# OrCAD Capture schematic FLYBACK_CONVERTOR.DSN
size A
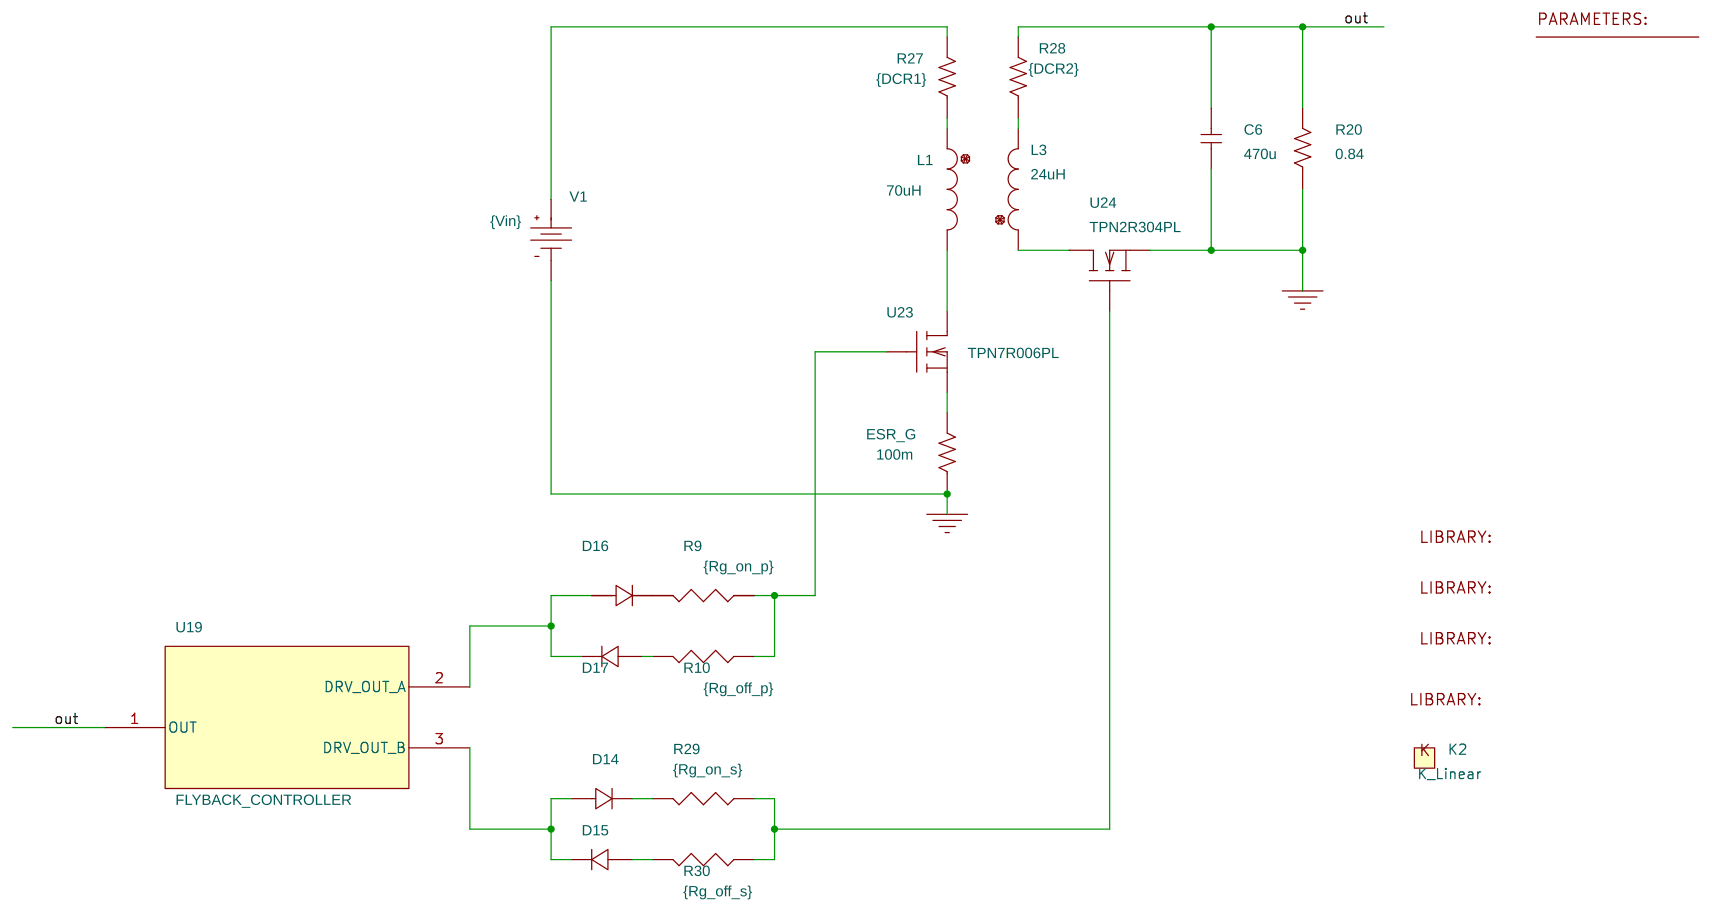
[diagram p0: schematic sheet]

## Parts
1  PARAM
C6  470u  [cap196]
D14  Diode_nom
D15  Diode_nom
D16  Diode_nom
D17  Diode_nom
ESR_G  100m  [AXRC05]
K2  K_Linear
L1  70uH  [DISC350x175LS200x100034]
L3  24uH  [DISC350x175LS200x100034]
LIB1  LIB
LIB2  LIB
LIB3  LIB
LIB4  LIB
R9  {Rg_on_p}  [AXRC05]
R10  {Rg_off_p}  [AXRC05]
R20  0.84  [AXRC05]
R27  {DCR1}  [AXRC05]
R28  {DCR2}  [AXRC05]
R29  {Rg_on_s}  [AXRC05]
R30  {Rg_off_s}  [AXRC05]
U19  FLYBACK_CONTROLLER
U23  TPN7R006PL
U24  TPN2R304PL
V1  VDC

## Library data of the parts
1 = PARAM: DCR1: 100m; DCR2: 100m; Fc: 100k; Rdrv_off_p: 0.5; Rdrv_off_s: 0.5; Rdrv_on_p: 5; Rg_off_p: 10; Rg_off_s: 0.1m; Rg_on_p: 10; Rg_on_s: 0.1m; Vdrv_H_p: 10; Vdrv_H_s: 5; Vin: 24; Vout: 5
C6 = C
D14-D17 = Diode_nom
ESR_G R20 R27 R28 = R_v2
K2 = K_Linear: L1: L1; L2: L3
L1 L3 = L
LIB1 = LIB: FILENAME: ../../../Lib/TPN7R006PL.lib
LIB2 = LIB: FILENAME: ../../../Lib/TPN2R304PL.lib
LIB3 = LIB: FILENAME: ../../../Lib/diode_nom.lib
LIB4 = LIB: FILENAME: ../../../Lib/Flyback_controller.lib
R9 R10 R29 R30 = R
U19 = FLYBACK_CONTROLLER
U23 = TPN7R006PL
U24 = TPN2R304PL
V1 = VDC: DC: {Vin}

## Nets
0: C6.1 ESR_G.1 R20.1 U24.0(s) V1.1(-)
out: C6.2 R20.2 R28.2 U19.1(OUT)
N2169419: R27.2 V1.0(+)
N2169537: L1.1 R27.1
N2169543: L3.2 R28.1
N2169657: L1.2 U23.2(d)
N2169663: L3.1 U24.2(d)
N2169723: R29.1 R30.1 U24.1(g)
N2169755: R9.1 R10.1 U23.1(g)
N2169879: D16.0(1) D17.1(2) U19.2(DRV_OUT_A)
N2169999: D17.0(1) R10.2
N2170035: D14.0(1) D15.1(2) U19.3(DRV_OUT_B)
N2170089: D14.1(2) R29.2
N2170169: D15.0(1) R30.2
N2170977: ESR_G.2 U23.0(s)
N2175457: D16.1(2) R9.2
